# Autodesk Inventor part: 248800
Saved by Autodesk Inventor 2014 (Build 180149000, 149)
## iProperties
Shininess: 21.0
Length Units: 11272
Angle Units: 11279
Time Units: 11290
Mass Units: 11286
Length Display Precision: 5
Angle Display Precision: 2
Company: Autodesk, Inc.
Created: 2001-04
Part Number: 248800
Project: 2039
Material: Steel, Mild
Description: ELECTRIC MOTOR; 50 HP
Document SubType Name: Modeling
Designer: Autodesk, Inc.
Density: 7.86 g/cm^3
Mass: 283949 g
Surface Area: 32991.4 cm^2
Volume: 36125.8 cm^3
Appearance: Blue (Flat)
Density: 7.86
Volumn: 10701.284002384873
Area: 6819.382059126692
PropertySet Name: Model Information
Control State: 0
Master: False
Checked Out: False
Last Check In By: JT
Last Check In Date: 2003-06-20
Title: ELECTRIC MOTOR; 50 HP
Author: Autodesk, Inc.
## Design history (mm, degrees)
sketch "Sketch1"
  geometry: C1 r 26.988 at (0, 0)
  constraints: 1 centre point, 1 other
  dimensions: "d0" = 53.975 diameter of C1 (= U)
extrude "Extrusion1" new body sketch "Sketch1" distance "d1" = 127; taper "d2" = 0 deg
chamfer "Chamfer1" distance "d3" = 1.5875; stored, may be unused: second distance "d4" = 1.5875, angle "d118" = 45 deg
workplane "Work Plane1"
sketch "Sketch2"
  geometry: L1 (0, 73.025)-(0, -249.238) reference; L2 (-275.59, 0)-(275.59, 0) reference; L3 (-196.85, -203.2)-(-127, -203.2); L4 (127, -203.2)-(196.85, -203.2); L5 (-127, -203.2)-(0, -36.653); L6 (0, -36.653)-(127, -203.2); L7 (-196.85, -180.975)-(-138.002, -180.975); L8 (-138.002, -180.975)-(0, 0); L9 (0, 0)-(138.002, -180.975); L10 (138.002, -180.975)-(196.85, -180.975); L11 (-196.85, -203.2)-(-196.85, -180.975); L12 (196.85, -203.2)-(196.85, -180.975)
  constraints: 20 end point, 3 collinear, 2 parallel, 2 perpendicular, 1 midpoint, 1 point on line, 3 other
  dimensions: "d6" = 203.2 distance between parallel lines of L2 L4 (= D); "d7" = 393.7 distance of L4.end L3.start; "d8" = 196.85 distance from line of L4.end L1 (= 0.5 x d7); "d9" = 69.85 distance of L3.start L3.end; "d10" = 22.225 distance of L3.start L7.start
extrude "Extrusion2" join sketch "Sketch2" distance "d11" = 374.65; taper "d12" = 0 deg
workplane "Work Plane2"
sketch "Sketch3"
  geometry: L1 (-127, -203.2)-(-196.85, -203.2) reference; L2 (-127, -184.15)-(-167.64, -184.15); C1 r 26.988 at (0, 0) reference; C2 r 184.15 at (0, 0)
  constraints: 2 end point, 1 centre point, 1 concentric, 1 tangent
  dimensions: "d14" = 19.05 distance between parallel lines of L2 L1 (= RIB_HEIGHT)
extrude "Extrusion3" join sketch "Sketch3" distance "d15" = 646.1125; taper "d16" = 0 deg
fillet "Fillet1" dims "d17" = 12.7
sketch "Sketch4"
  geometry: L1 (0, -726.121)-(0, -112.079) reference; L2 (-203.2, -606.425)-(-180.975, -606.425) reference; L3 (0, -206.375)-(-184.15, -206.375); L4 (-215.9, -238.125)-(-215.9, -600.075); L5 (-184.15, -631.825)-(0, -631.825); L6 (0, -631.825)-(0, -206.375); A1 r 31.75 centre (-184.15, -238.125) between (-184.15, -206.375) and (-215.9, -238.125); A2 r 31.75 centre (-184.15, -600.075) between (-215.9, -600.075) and (-184.15, -631.825)
  constraints: 8 end point, 4 point on circle, 4 tangent, 2 centre point, 2 parallel, 1 collinear, 1 equal radius, 1 horizontal, 1 perpendicular
  dimensions: "d19" = 25.4 distance between parallel lines of L5 L2 (= RIB_FROMBACK); "d20" = 31.75 radius of A1; "d86" = 215.9 distance between parallel lines of L4 L1; "d87" = 361.95 distance of A1.centre A2.centre
extrude "Extrusion4" join sketch "Sketch4" stored distance "d21" = 6.35; taper "d22" = 0 deg
sketch "Sketch5"
  geometry: L1 (-203.2, -606.425)-(-180.975, -606.425) reference; L2 (0, -884.844)-(0, -130.338) reference; L3 (0, -773.112)-(-190.5, -773.112); L4 (-209.55, -754.062)-(-209.55, -631.825); L5 (0, -768.35)-(-190.5, -768.35); L6 (-204.787, -754.062)-(-204.787, -631.825); L7 (-204.787, -631.825)-(-209.55, -631.825); L8 (0, -768.35)-(0, -773.112); L9 (184.15, -773.112)-(-184.15, -773.112) reference; L10 (-215.9, -238.125)-(-215.9, -600.075) reference; A1 r 19.05 centre (-190.5, -754.062) between (-209.55, -754.062) and (-190.5, -773.112); A2 r 14.288 centre (-190.5, -754.062) between (-204.787, -754.062) and (-190.5, -768.35)
  constraints: 12 end point, 5 perpendicular, 4 point on circle, 4 tangent, 2 centre point, 1 collinear, 1 point on line, 2 other
  dimensions: "d27" = 19.05 radius of A1; "d29" = 4.7625 distance of L6.end L4.end; "d31" = 25.4 distance between parallel lines of L7 L1 (= RIB_FROMBACK); "d88" = 6.35 distance between parallel lines of L4 L10
revolve "Revolution1" sketch "Sketch5" stored, may be unused: angle "d30" = 90 deg
sketch "Sketch6"
  geometry: L1 (171.45, 231.775)-(222.25, 231.775) reference; L2 (323.85, 0)-(393.7, 0) reference; L3 (393.7, 0)-(393.7, -374.65) reference; L4 (196.85, -495.935)-(196.85, 353.06) reference; L5 (0, 0)-(69.85, 0) reference; C1 r 8.331 at (38.1, -34.925); C2 r 8.331 at (38.1, -339.725); C3 r 8.331 at (355.6, -339.725); C4 r 8.331 at (355.6, -34.925)
  constraints: 4 centre point, 3 equal radius, 2 horizontal alignment, 2 vertical alignment
  dimensions: "d33" = 158.75 distance from line of L4 C4.centre; "d35" = 317.5 distance of C1.centre C4.centre (= 2 x d33); "d37" = 16.6624 diameter of C1 (= H); "d39" = 304.8 distance of C2.centre C1.centre (= F2); "d79" = 34.925 distance from line of L5 C1.centre
extrude "Extrusion5" cut sketch "Sketch6" distance "d40" = 22.225 (= G); taper "d41" = 0 deg
workplane "Work Plane6"
sketch "Sketch15"
  geometry: L1 (-196.85, -203.2)-(-127, -203.2) reference; L2 (-196.85, -180.975)-(-196.85, -203.2) reference; L3 (-138.002, -180.975)-(-196.85, -180.975) reference; L4 (-111.662, -146.433)-(-138.002, -180.975) reference; L5 (-127, -203.2)-(-93.173, -158.84) reference; L6 (93.173, -158.84)-(127, -203.2) reference; L7 (138.002, -180.975)-(111.662, -146.433) reference; L8 (196.85, -180.975)-(138.002, -180.975) reference; L9 (196.85, -203.2)-(196.85, -180.975) reference; L10 (127, -203.2)-(196.85, -203.2) reference; A1 r 184.15 centre (0, 0) between (-111.662, -146.433) and (-93.173, -158.84) reference; A2 r 184.15 centre (0, 0) between (93.173, -158.84) and (111.662, -146.433) reference
extrude "Extrusion13" cut sketch "Sketch15" distance "d77" = 146.05; taper "d78" = 0 deg
workplane "Work Plane3"
sketch "Sketch7"
  geometry: L1 (-403.228, 149.352)-(-215.9, 149.352); L2 (-215.9, 149.352)-(-215.9, -104.648); L3 (-215.9, -104.648)-(-425.45, -104.648); L4 (0, 257.81)-(0, -257.81) reference; L5 (-547.37, 0)-(306.07, 0) reference; L6 (-425.45, -104.648)-(-403.228, 149.352); C1 r 184.15 at (0, 0) reference
  constraints: 8 end point, 1 horizontal, 1 parallel, 1 perpendicular
  dimensions: "d45" = 104.648 distance between parallel lines of L3 L5; "d91" = 215.9 distance between parallel lines of L2 L4; "d93" = 254 distance between parallel lines of L3 L1; "d94" = 425.45 distance from line of L4 L3.end; "d95" = 85 deg angle of L1 L6
extrude "Extrusion6" join sketch "Sketch7" stored distance "d47" = 177.8 (= XN); taper "d48" = 0 deg
sketch "Sketch8"
  geometry: L1 (0, 254)-(0, 0) reference; L2 (177.8, 0)-(177.8, 254) reference; L3 (177.8, 254)-(0, 254) reference; L4 (-484.823, 104.648)-(597.535, 104.648) reference; L5 (165.1, 215.9)-(165.1, 38.1); L6 (12.7, 38.1)-(12.7, 215.9); L7 (12.7, 215.9)-(165.1, 215.9); L8 (165.1, 38.1)-(12.7, 38.1)
  constraints: 8 end point, 1 parallel
  dimensions: "d49" = 38.1 distance between parallel lines of L3 L7; "d50" = 12.7 distance between parallel lines of L2 L5; "d51" = 111.252 distance between parallel lines of L7 L4 (derived); "d52" = 177.8 distance of L6.start L6.end; "d97" = 12.7 distance between parallel lines of L1 L6
extrude "Extrusion7" join sketch "Sketch8" stored distance "d53" = 177.8 (= XN); taper "d54" = 0 deg
fillet "Fillet3" dims "d55" = 12.7
node "SPlane"
sketch "Sketch9"
  geometry: C1 r 26.988 at (0, 0) reference; C2 r 53.975 at (0, 0)
  constraints: 1 centre point, 1 concentric
  dimensions: "d57" = 107.95 diameter of C2 (= 2 x U)
extrude "Extrusion8" join sketch "Sketch9" stored distance "d58" = 25.4; taper "d59" = 0 deg
fillet "Fillet4" dims "d60" = 3.175
sketch "Sketch10"
  geometry: L1 (26.988, -1.587)-(-26.988, -1.587) reference; L2 (26.988, -1.587)-(26.988, -98.425); L3 (20.638, -1.587)-(20.638, -84.226); L4 (20.638, -1.587)-(20.638, 0); L5 (20.638, 0)-(26.988, 0); L6 (26.988, 0)-(26.988, -1.587); L7 (-25.4, 0)-(25.4, 0) reference; A1 r 19.05 centre (39.688, -84.226) between (20.638, -84.226) and (26.988, -98.425)
  constraints: 10 end point, 3 collinear, 2 point on circle, 1 centre point, 1 parallel, 1 perpendicular, 1 point on line, 1 tangent
  dimensions: "SlotDepth" = 6.35 distance between parallel lines of L2 L3; "d63" = 12.7 distance from line of L2 A1.centre (derived); "SlotLength" = 98.425 distance of L5.end L2.end
extrude "Keyway" cut sketch "Sketch10" taper "d66" = 0 deg; stored distance "SlotWidth" = 12.7
sketch "Sketch12"
  geometry: L1 (207.097, 197.68)-(67.782, 197.68); L2 (67.782, 197.68)-(67.782, -14.868); L3 (67.782, -14.868)-(207.097, -14.868); L4 (207.097, -14.868)-(207.097, 197.68)
  constraints: 8 end point, 2 parallel, 1 horizontal, 1 perpendicular
extrude "Extrusion11" cut sketch "Sketch12" distance "d70" = 152.4; taper "d71" = 0 deg
sketch "Sketch13"
  geometry: C1 r 165.1 at (0, 0); A1 r 184.15 centre (0, 0) between (93.173, -158.84) and (111.662, -146.433) reference
  constraints: 1 centre point, 1 coincident
  dimensions: "d72" = 330.2 diameter of C1
extrude "Extrusion12" cut sketch "Sketch13" distance "d73" = 508; taper "d74" = 0 deg
sketch "Sketch16"
  geometry: L1 (-171.45, -127)-(171.45, -127) reference; C1 r 25.4 at (0, -419.1); C2 r 8.331 at (-158.75, -266.7) reference; 4 further points; 1 other entity
  constraints: 1 centre point, 1 vertical alignment, 1 other
  dimensions: "d81" = 50.8 diameter of C1; "d96" = 292.1 distance from line of C1.centre L1
extrude "Extrusion14" join sketch "Sketch16" distance "d82" = 220.6625; taper "d83" = 0 deg
sketch "Sketch17"
  geometry: L1 (-127, -203.2)-(-196.85, -203.2) reference; L2 (196.85, -203.2)-(127, -203.2) reference; L3 (-196.85, -203.2)-(235.146, -203.2); L4 (235.146, -203.2)-(235.146, -321.096); L5 (235.146, -321.096)-(-196.85, -321.096); L6 (-196.85, -321.096)-(-196.85, -203.2)
  constraints: 8 end point, 2 parallel, 1 horizontal, 1 perpendicular
extrude "Extrusion15" cut sketch "Sketch17" stored distance "d89" = 25.4; taper "d90" = 0 deg
sketch "Sketch19"
  geometry: L1 (0, -393.7)-(0, -444.5) reference; L2 (0, -419.1)-(253.206, -419.1); L3 (220.662, -393.7)-(220.662, -444.5) reference; C1 r 16.669 at (253.206, -419.1); C2 r 29.369 at (253.206, -419.1)
  constraints: 2 centre point, 2 end point, 1 coincident, 1 midpoint, 1 perpendicular
  dimensions: "d104" = 12.7 radial gap between concentric circles of C2 C1; "d105" = 58.7375 diameter of C2; "d106" = 32.54375 distance from line of L2.end L3 (derived)
extrude "Extrusion17" join sketch "Sketch19" distance "d107" = 12.7; taper "d108" = 0 deg
sketch "Sketch20"
  geometry: L1 (204.787, -631.825)-(-203.2, -631.825) reference; C1 r 15.875 at (0, -631.825); 1 further point
  constraints: 1 centre point, 1 point on line, 1 vertical alignment
  dimensions: "d109" = 31.75 diameter of C1
extrude "Extrusion18" join sketch "Sketch20" distance "d110" = 254; taper "d111" = 0 deg
sketch "Sketch21"
  geometry: L1 (-50.8, 38.1)-(50.8, 38.1); L2 (50.8, 38.1)-(50.8, -38.1); L3 (50.8, -38.1)-(-50.8, -38.1); L4 (-50.8, -38.1)-(-50.8, 38.1); C1 r 15.875 at (0, 0) reference
  constraints: 8 end point, 2 parallel, 1 horizontal, 1 perpendicular
  dimensions: "d112" = 76.2 distance of L1.end L2.end; "d113" = 101.6 distance of L1.start L1.end; "d114" = 50.8 distance from line of L2 C1.centre; "d115" = 38.1 distance from line of C1.centre L1
extrude "Extrusion19" join sketch "Sketch21" distance "d116" = 50.8; taper "d117" = 0 deg
body "Solid1"
pattern_circular "Circular Pattern1" dims angle "d26" = 360 deg
other parameters: "NW" = 133.35 [user parameter; used in 1 equation term], "U" = 53.975 [user parameter; used in 2 equation terms], "E_DIM" = 158.75 [user parameter], "H" = 16.6624 [user parameter; used in 1 equation term], "BA" = 133.35 [user parameter; used in 1 equation term], "F2" = 304.8 [user parameter; used in 1 equation term], "A" = 393.7 [user parameter], "B" = 350.52 [user parameter], "C" = 813.308 [user parameter; used in 1 equation term], "D" = 203.2 [user parameter; used in 1 equation term], "G" = 22.225 [user parameter; used in 1 equation term], "J_DIM" = 48.26 [user parameter], "S" = 120.65 [user parameter; used in 1 equation term], "d5" = -231.775, "d13" = -813.308 (= -C), "RIB_HEIGHT" = 19.05 [user parameter; used in 1 equation term], "RIB_FROMFRONT" = 25.4 [user parameter], "RIB_FROMBACK" = 25.4 [user parameter; used in 2 equation terms], "d32" = 278.98473, "BS" = 152.4 [user parameter; used in 1 equation term], "AF" = 163.5125 [user parameter], "XL" = 257.048 [user parameter], "XN" = 177.8 [user parameter; used in 2 equation terms], "d42" = -419.1 (= -BS - NW - BA), "AB" = 387.35 [user parameter], "d56" = -120.65 (= -S), "d76" = -114.3
